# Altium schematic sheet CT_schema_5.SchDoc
size 221 x 258 mm
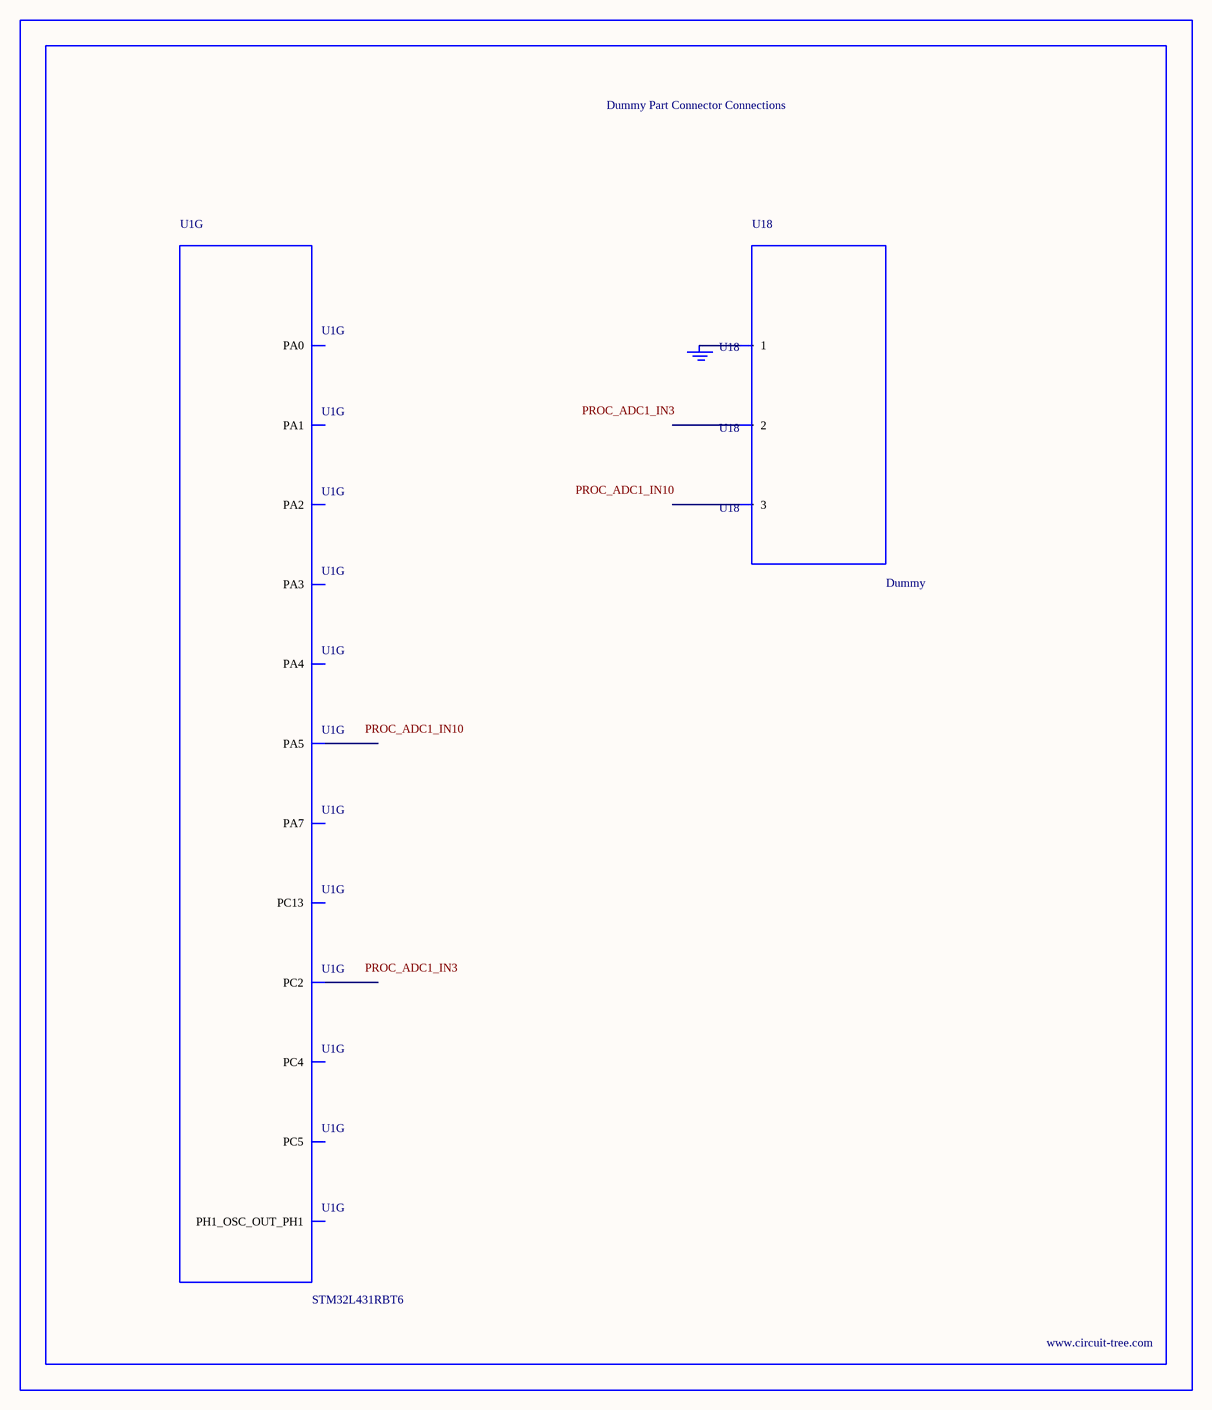
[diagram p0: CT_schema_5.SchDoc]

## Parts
BORDER4  (no value)
GND_INSTANCE_4_0  (no value)
U1  STM32L431RBT6  [LQFP64]  (part G of 7)
U18  Dummy  [DUMMY_PACKAGE_176]

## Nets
NetGND_INSTANCE_4_0_0: GND_INSTANCE_4_0.0(GND) U18.1

Not connected (* = marked no-connect by the designer): U1 2(PC13) 6(PH1_OSC_OUT_PH1) 10(PC2) 14(PA0) 15(PA1) 16(PA2) 17(PA3) 20(PA4) 21(PA5) 23(PA7) 24(PC4) 25(PC5); U18 2 3

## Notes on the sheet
- Labels drawn without touching a wire or pin: PROC_ADC1_IN3, PROC_ADC1_IN10

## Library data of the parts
BORDER4 = BORDER_PAGE4
GND_INSTANCE_4_0 = GND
